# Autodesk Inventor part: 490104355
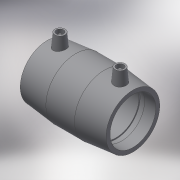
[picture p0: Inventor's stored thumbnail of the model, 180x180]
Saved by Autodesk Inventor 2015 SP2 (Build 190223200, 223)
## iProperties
Created: 2017-06
Part Number: 490104355
Material: Generic
Description: PLASSON COUPLER 355-355
Document SubType Name: Modeling
Designer: KIM
Mass: 10772.6 g
Surface Area: 7789.85 cm^2
Volume: 10772.6 cm^3
Density: 1 g/cm^3
Appearance: Default
Author: KIM
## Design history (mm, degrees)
derived "490104.ipt"
feature "Solid1::490104.ipt"
tag "TaggingFeature1"
body "Solid1"
other parameters: "d0" = 277, "d1" = 355, "d2" = 431, "d3" = 137, "d4" = 92.33333, "d5" = 387.9, "d6" = 337.25, "d7" = 355, "d8" = 168 deg, "d10" = 54.8, "d11" = 18.26667, "d13" = 277, "d14" = 17.6296, "d15" = 137, "d16" = 137, "d17" = 337.25, "d18" = 355, "d19" = 3.52592, "d20" = 168 deg, "d22" = 405.14, "d23" = 431, "d24" = 392.9858, "d25" = 135 deg, "d26" = 152.35, "d27" = 135 deg, "d29" = 203, "d30" = 14, "d31" = 96.95, "d34" = 5 deg, "d35" = 15, "d39" = 5 deg, "d41" = 4, "d42" = 14, "d43" = 0, "d45" = 4, "d46" = 14, "d47" = 0, "d48" = 3, "d49" = 0, "d50" = 3, "d51" = 0, "d52" = 39.73, "d53" = 9.9325, "d_" = 355, "L_" = 277, "L_1" = 137, "D_" = 431, "A_" = 203, "d_2" = 12
